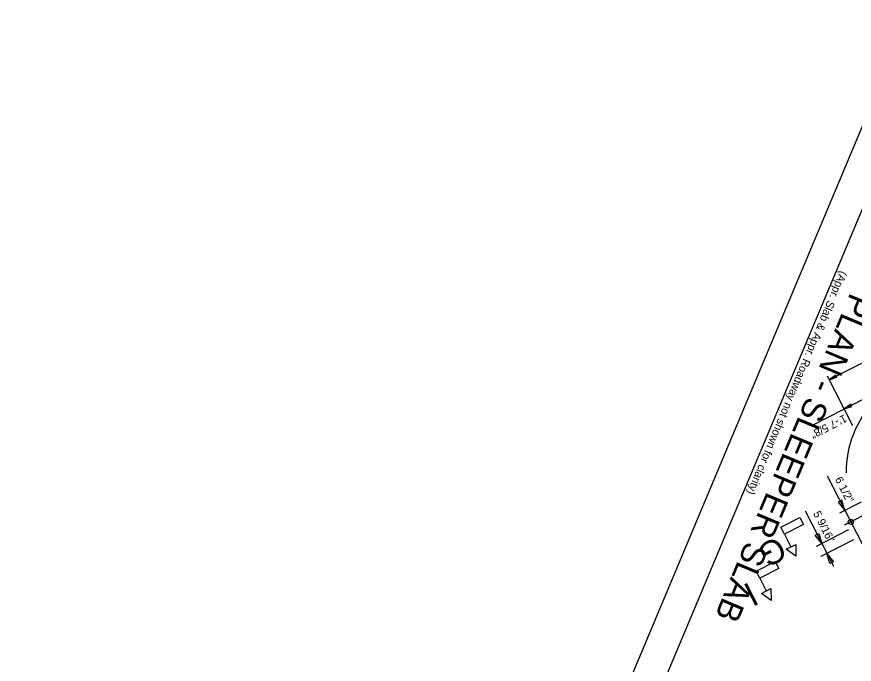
# Model space of a CAD drawing. Extents: x 1968564 to 1968711, y 796599 to 796794.
# Drawn here: x 1968563.8 to 1968616.2, y 796725.3 to 796765.7 of the extents above; entities that cross this region are included whole.
import ezdxf

# ---------------------------------------------------------------- set-up
doc = ezdxf.new("R2010")
doc.units = 0
for name, color, linetype in [('BR_AUTO DIMENSION', 7, 'Continuous'), ('BR_BORDER LINES', 7, 'Continuous'), ('BR_TABLE LINES', 7, 'Continuous'), ('BR_TEXT', 7, 'Continuous'), ('Level 31', 7, 'Continuous')]:
    doc.layers.add(name, color=color, linetype=linetype)

msp = doc.modelspace()

# ---------------------------------------------------------------- linework, layer by layer
at = {"layer": 'BR_AUTO DIMENSION'}
for p, q in [((1968621.161, 796746.392), (1968614.613, 796743.039)), ((1968616.085, 796740.164), (1968614.499, 796743.262)), ((1968618.755, 796742.864), (1968615.417, 796741.155)), ((1968615.417, 796741.155), (1968613.619, 796740.235)), ((1968614.48, 796737.033), (1968617.659, 796730.824)), ((1968616.605, 796735.4), (1968615.245, 796734.703)), ((1968618.118, 796735.262), (1968615.548, 796733.946)), ((1968613.104, 796734.842), (1968614.871, 796731.39)), ((1968615.809, 796733.658), (1968613.789, 796732.624)), ((1968616.12, 796733.036), (1968614.083, 796731.993))]:
    msp.add_line(p, q, dxfattribs=at)
for points in [[(1968615.023, 796743.334), (1968614.613, 796743.039), (1968615.092, 796743.2)], [(1968615.955, 796741.515), (1968615.544, 796741.22), (1968616.023, 796741.381)], [(1968615.176, 796735.399), (1968615.584, 796734.877), (1968615.399, 796735.512)], [(1968613.96, 796733.442), (1968614.146, 796732.807), (1968613.738, 796733.328)], [(1968614.644, 796731.551), (1968614.463, 796732.187), (1968614.868, 796731.664)]]:
    msp.add_lwpolyline(points, close=True, dxfattribs=at)
msp.add_circle((1968615.954, 796734.154), 0.159, dxfattribs=at)
msp.add_arc((1968622.193, 796737.267), 6.527, 136.8064, 180.4125, dxfattribs=at)
at = {"layer": 'BR_BORDER LINES'}
msp.add_line((1968618.549, 796758.212), (1968566.464, 796634.028), dxfattribs=at)
at = {"layer": 'BR_TABLE LINES'}
for p, q in [((1968611.814, 796733.391), (1968612.219, 796732.6)), ((1968610.266, 796730.634), (1968610.671, 796729.843))]:
    msp.add_line(p, q, dxfattribs=at)
for points in [[(1968612.778, 796734.434), (1968613.001, 796733.999), (1968611.814, 796733.391), (1968611.591, 796733.827)], [(1968612.516, 796732.752), (1968612.523, 796732.007), (1968611.923, 796732.448)], [(1968611.23, 796731.677), (1968611.453, 796731.242), (1968610.266, 796730.634), (1968610.043, 796731.07)], [(1968610.968, 796729.995), (1968610.975, 796729.25), (1968610.374, 796729.691)]]:
    msp.add_lwpolyline(points, close=True, dxfattribs=at)
at = {"layer": 'Level 31'}
msp.add_lwpolyline([(1968619.541, 796765.748), (1968563.846, 796632.955), (1968644.997, 796598.919), (1968700.693, 796731.712)], close=True, dxfattribs=at)

# ---------------------------------------------------------------- texts
at = {"layer": 'BR_AUTO DIMENSION'}
for s, rotation, p in [('1\'-7 5/8"', 207.1148, (1968615.55, 796740.894)), ('6 1/2"', 297.1148, (1968614.944, 796736.827)), ('5 9/16"', 297.1148, (1968613.58, 796734.689))]:
    msp.add_text(s, height=0.5, rotation=rotation, dxfattribs=at).set_placement(p)
at = {"layer": 'BR_TEXT'}
for s, height, rotation, p in [('(Appr. Slab & Appr. Roadway not shown for clarity)', 0.49995, 247.246, (1968615.297, 796749.895)), ('PLAN - SLEEPER SLAB', 1.5, 247.246, (1968615.94, 796748.544)), ('G', 1.5, 207.1148, (1968611.41, 796733.298)), ('I', 1.5, 207.1148, (1968609.631, 796730.422))]:
    msp.add_text(s, height=height, rotation=rotation, dxfattribs=at).set_placement(p)

doc.saveas('drawing.dxf')
